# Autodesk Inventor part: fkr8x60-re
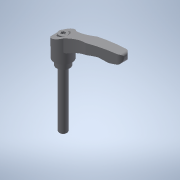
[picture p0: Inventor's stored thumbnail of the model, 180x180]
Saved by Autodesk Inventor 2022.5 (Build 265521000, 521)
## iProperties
Created: 2017-09
Part Number: fkr8x60-re
Material: 一般
Document SubType Name: Modeling
Designer: imaocorp
Density: 1 g/cm^3
Appearance: 既定
Author: imaocorp
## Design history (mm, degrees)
node "fkr8x60-re.x_t1"
node "fkr8x60-re"
node "Base1"
